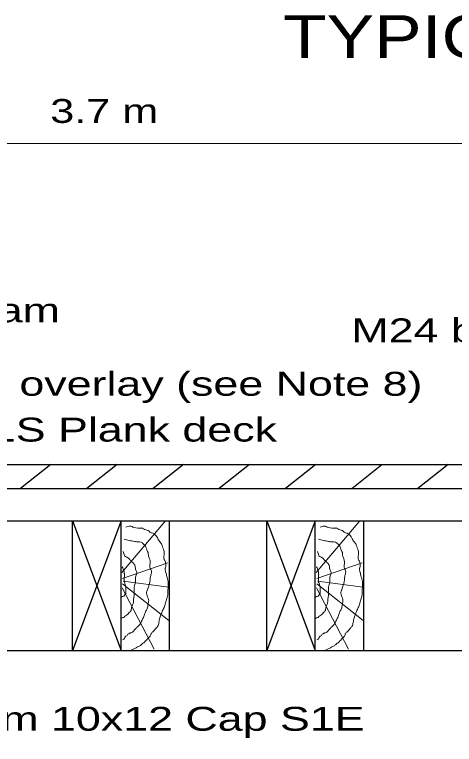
# Model space of a CAD drawing. Extents: x 13426 to 15509, y -9298 to -5111.
# Drawn here: x 15374.08 to 15398.12, y -5515.72 to -5475.82 of the extents above; entities that cross this region are included whole.
import ezdxf
from ezdxf.enums import TextEntityAlignment as Align

# ---------------------------------------------------------------- set-up
doc = ezdxf.new("R2010")
doc.units = 0
doc.header["$LTSCALE"] = 0.52
for name, color, linetype, lineweight in [('1', 7, 'Continuous', 13), ('20', 7, 'Continuous', 13), ('4', 7, 'Continuous', 13)]:
    doc.layers.add(name, color=color, linetype=linetype, lineweight=lineweight)
doc.layers.add('19', color=7, linetype='Continuous')

msp = doc.modelspace()

# ---------------------------------------------------------------- linework, layer by layer
at = {"layer": '1'}
msp.add_line((15412.258, -5482.878), (15347.53, -5482.878), dxfattribs=at)
at = {"layer": '1', "lineweight": 25}
msp.add_lwpolyline([(15342.717, -5510.579), (15417.071, -5510.579), (15417.071, -5515.89)], dxfattribs=at)
at = {"layer": '4', "lineweight": 25}
for p, q in [((15347.53, -5500.409), (15412.258, -5500.409)), ((15376.065, -5500.409), (15374.408, -5501.728)), ((15379.684, -5500.409), (15378.028, -5501.728)), ((15383.304, -5500.409), (15381.647, -5501.728)), ((15386.923, -5500.409), (15385.266, -5501.728)), ((15390.543, -5500.409), (15388.885, -5501.728)), ((15392.505, -5501.728), (15394.162, -5500.409)), ((15397.781, -5500.409), (15396.124, -5501.728)), ((15348.028, -5501.728), (15411.76, -5501.728)), ((15348.028, -5503.498), (15411.76, -5503.498)), ((15377.239, -5510.579), (15377.239, -5503.498)), ((15377.239, -5503.498), (15379.894, -5510.579)), ((15379.894, -5503.498), (15377.239, -5510.579)), ((15379.894, -5510.579), (15379.894, -5503.498)), ((15382.55, -5510.579), (15382.55, -5503.498)), ((15387.86, -5510.579), (15387.86, -5503.498)), ((15387.86, -5503.498), (15390.516, -5510.579)), ((15390.516, -5503.498), (15387.86, -5510.579)), ((15390.516, -5510.579), (15390.516, -5503.498)), ((15393.172, -5510.579), (15393.172, -5503.498))]:
    msp.add_line(p, q, dxfattribs=at)
at = {"layer": '4'}
for p, q in [((15382.325, -5503.497), (15379.946, -5506.317)), ((15392.947, -5503.497), (15390.569, -5506.317)), ((15382.456, -5505.79), (15379.98, -5506.657)), ((15393.078, -5505.79), (15390.601, -5506.657)), ((15382.505, -5507.116), (15380.012, -5506.793)), ((15393.128, -5507.116), (15390.634, -5506.793)), ((15381.702, -5510.514), (15379.963, -5507.15)), ((15382.505, -5508.951), (15379.98, -5506.946)), ((15392.324, -5510.514), (15390.585, -5507.15)), ((15393.128, -5508.951), (15390.601, -5506.946))]:
    msp.add_line(p, q, dxfattribs=at)
for points in [[(15380.16, -5503.837), (15380.389, -5503.786), (15380.603, -5503.854), (15381.013, -5503.888), (15381.046, -5503.888), (15381.128, -5503.939), (15381.374, -5504.024), (15381.472, -5504.108), (15381.538, -5504.159), (15381.554, -5504.159), (15381.816, -5504.312), (15381.882, -5504.414), (15382.013, -5504.652), (15382.079, -5504.72), (15382.161, -5504.907), (15382.259, -5505.179), (15382.259, -5505.281), (15382.243, -5505.57), (15382.325, -5505.756), (15382.341, -5505.926), (15382.325, -5506.062), (15382.309, -5506.113), (15382.309, -5506.164), (15382.325, -5506.232), (15382.341, -5506.317), (15382.374, -5506.436), (15382.391, -5506.521), (15382.44, -5506.674), (15382.473, -5506.81), (15382.473, -5506.929), (15382.473, -5507.116), (15382.456, -5507.32), (15382.44, -5507.608), (15382.358, -5507.863), (15382.292, -5508.118), (15382.194, -5508.339), (15382.095, -5508.577), (15382.013, -5508.798), (15381.964, -5509.052), (15381.898, -5509.273), (15381.784, -5509.392), (15381.653, -5509.545), (15381.538, -5509.664), (15381.521, -5509.732), (15381.489, -5509.8), (15381.423, -5509.868), (15381.325, -5509.97), (15381.242, -5510.055), (15381.144, -5510.157), (15381.046, -5510.225), (15380.931, -5510.327), (15380.75, -5510.412), (15380.685, -5510.463), (15380.603, -5510.497), (15380.521, -5510.53), (15380.373, -5510.582), (15380.372, -5510.582)], [(15390.782, -5503.837), (15391.012, -5503.786), (15391.225, -5503.854), (15391.635, -5503.888), (15391.667, -5503.888), (15391.749, -5503.939), (15391.996, -5504.024), (15392.094, -5504.108), (15392.16, -5504.159), (15392.176, -5504.159), (15392.439, -5504.312), (15392.504, -5504.414), (15392.635, -5504.652), (15392.701, -5504.72), (15392.783, -5504.907), (15392.882, -5505.179), (15392.882, -5505.281), (15392.865, -5505.57), (15392.947, -5505.756), (15392.964, -5505.926), (15392.947, -5506.062), (15392.931, -5506.113), (15392.931, -5506.164), (15392.947, -5506.232), (15392.964, -5506.317), (15392.996, -5506.436), (15393.013, -5506.521), (15393.062, -5506.674), (15393.095, -5506.81), (15393.095, -5506.929), (15393.095, -5507.116), (15393.078, -5507.32), (15393.062, -5507.608), (15392.98, -5507.863), (15392.914, -5508.118), (15392.816, -5508.339), (15392.717, -5508.577), (15392.635, -5508.798), (15392.586, -5509.052), (15392.52, -5509.273), (15392.406, -5509.392), (15392.274, -5509.545), (15392.16, -5509.664), (15392.143, -5509.732), (15392.11, -5509.8), (15392.045, -5509.868), (15391.946, -5509.97), (15391.864, -5510.055), (15391.766, -5510.157), (15391.667, -5510.225), (15391.553, -5510.327), (15391.372, -5510.412), (15391.307, -5510.463), (15391.225, -5510.497), (15391.143, -5510.53), (15390.995, -5510.582), (15390.994, -5510.582)], [(15380.061, -5504.499), (15380.34, -5504.567), (15380.635, -5504.618), (15380.734, -5504.635), (15380.865, -5504.652), (15380.914, -5504.652), (15381.062, -5504.703), (15381.078, -5504.72), (15381.16, -5504.805), (15381.275, -5504.975), (15381.325, -5505.128), (15381.374, -5505.23), (15381.39, -5505.383), (15381.456, -5505.57), (15381.489, -5505.739), (15381.472, -5505.96), (15381.489, -5506.096), (15381.554, -5506.232), (15381.554, -5506.351), (15381.505, -5506.538), (15381.489, -5506.708), (15381.341, -5507.251), (15381.292, -5507.455), (15381.374, -5507.727), (15381.407, -5507.863), (15381.374, -5508.033), (15381.341, -5508.254), (15381.259, -5508.424), (15381.177, -5508.611), (15381.095, -5508.832), (15381.046, -5508.933), (15380.947, -5509.121), (15380.816, -5509.273), (15380.685, -5509.392), (15380.455, -5509.613), (15380.389, -5509.63), (15380.324, -5509.664), (15380.275, -5509.698), (15380.225, -5509.766), (15380.11, -5509.851), (15380.11, -5509.885), (15380.061, -5509.953), (15380.045, -5509.97), (15379.98, -5510.004)], [(15390.683, -5504.499), (15390.962, -5504.567), (15391.258, -5504.618), (15391.356, -5504.635), (15391.487, -5504.652), (15391.536, -5504.652), (15391.684, -5504.703), (15391.701, -5504.72), (15391.783, -5504.805), (15391.897, -5504.975), (15391.946, -5505.128), (15391.996, -5505.23), (15392.012, -5505.383), (15392.078, -5505.57), (15392.11, -5505.739), (15392.094, -5505.96), (15392.11, -5506.096), (15392.176, -5506.232), (15392.176, -5506.351), (15392.127, -5506.538), (15392.11, -5506.708), (15391.963, -5507.251), (15391.913, -5507.455), (15391.996, -5507.727), (15392.028, -5507.863), (15391.996, -5508.033), (15391.963, -5508.254), (15391.881, -5508.424), (15391.799, -5508.611), (15391.717, -5508.832), (15391.667, -5508.933), (15391.569, -5509.121), (15391.438, -5509.273), (15391.307, -5509.392), (15391.077, -5509.613), (15391.012, -5509.63), (15390.946, -5509.664), (15390.897, -5509.698), (15390.847, -5509.766), (15390.733, -5509.851), (15390.733, -5509.885), (15390.683, -5509.953), (15390.667, -5509.97), (15390.601, -5510.004)], [(15380.012, -5505.179), (15380.045, -5505.281), (15380.094, -5505.4), (15380.209, -5505.485), (15380.258, -5505.502), (15380.34, -5505.57), (15380.455, -5505.705), (15380.553, -5505.79), (15380.619, -5505.875), (15380.668, -5505.978), (15380.701, -5506.198), (15380.767, -5506.317), (15380.75, -5506.419), (15380.685, -5506.623), (15380.685, -5506.827), (15380.619, -5507.116), (15380.619, -5507.541), (15380.586, -5507.761), (15380.57, -5507.965), (15380.504, -5508.135), (15380.455, -5508.339), (15380.422, -5508.441), (15380.357, -5508.492), (15380.291, -5508.577), (15380.094, -5508.73), (15380.045, -5508.781), (15380.012, -5508.781), (15379.898, -5508.832)], [(15390.634, -5505.179), (15390.667, -5505.281), (15390.716, -5505.4), (15390.831, -5505.485), (15390.88, -5505.502), (15390.962, -5505.57), (15391.077, -5505.705), (15391.176, -5505.79), (15391.241, -5505.875), (15391.29, -5505.978), (15391.323, -5506.198), (15391.389, -5506.317), (15391.372, -5506.419), (15391.307, -5506.623), (15391.307, -5506.827), (15391.241, -5507.116), (15391.241, -5507.541), (15391.208, -5507.761), (15391.192, -5507.965), (15391.126, -5508.135), (15391.077, -5508.339), (15391.044, -5508.441), (15390.979, -5508.492), (15390.913, -5508.577), (15390.716, -5508.73), (15390.667, -5508.781), (15390.634, -5508.781), (15390.519, -5508.832)], [(15379.963, -5506.011), (15380.012, -5506.13), (15380.028, -5506.198), (15380.061, -5506.266), (15380.061, -5506.334), (15380.078, -5506.402), (15380.078, -5506.453), (15380.078, -5506.521), (15380.061, -5506.691), (15380.078, -5506.844), (15380.127, -5506.98), (15380.16, -5507.132), (15380.16, -5507.439), (15380.143, -5507.506), (15380.127, -5507.506), (15380.094, -5507.574), (15379.996, -5507.625), (15379.93, -5507.659), (15379.881, -5507.693)], [(15390.585, -5506.011), (15390.634, -5506.13), (15390.651, -5506.198), (15390.683, -5506.266), (15390.683, -5506.334), (15390.7, -5506.402), (15390.7, -5506.453), (15390.7, -5506.521), (15390.683, -5506.691), (15390.7, -5506.844), (15390.749, -5506.98), (15390.782, -5507.132), (15390.782, -5507.439), (15390.765, -5507.506), (15390.749, -5507.506), (15390.716, -5507.574), (15390.618, -5507.625), (15390.552, -5507.659), (15390.503, -5507.693)]]:
    msp.add_spline(points, degree=3, dxfattribs=at)

# ---------------------------------------------------------------- texts
at = {"layer": '19', "width": 1.35}
msp.add_text('3.7 m', height=1.307, dxfattribs=at).set_placement((15378.9755, -5481.744), align=Align.CENTER)
at = {"layer": '19', "width": 1.4}
msp.add_text('M24 bolts', height=1.307, dxfattribs=at).set_placement((15403.098, -5493.738), align=Align.RIGHT)
msp.add_text('4.3 m 10x12 Cap S1E', height=1.307, dxfattribs=at).set_placement((15369.27, -5514.971))
at = {"layer": '20'}
for s, height, width, p in [('TYPICAL SECTION-TWO LANE BRIDGE', 2.333, 1.25, (15424.934, -5478.191)), ('C Thrie beam', 1.307, 1.4, (15369.145, -5492.641)), ('ACP overlay (see Note 8)', 1.307, 1.4, (15382.5005, -5496.658))]:
    msp.add_text(s, height=height, dxfattribs=dict(at, width=width)).set_placement(p, align=Align.CENTER)
at = {"layer": '20', "width": 1.4}
msp.add_text('4x12 S1S Plank deck', height=1.307, dxfattribs=at).set_placement((15365.161, -5499.163))

doc.saveas('drawing.dxf')
